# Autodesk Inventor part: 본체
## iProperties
Created: 2014-12
Part Number: 본체
Document SubType Name: Modeling
Designer: elite
Density: 2.71 g/cm^3
Material: 알루미늄-6061
Mass: 613.432 g
Surface Area: 665.172 cm^2
Volume: 226.359 cm^3
Author: elite
